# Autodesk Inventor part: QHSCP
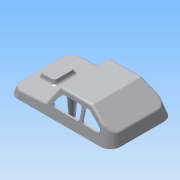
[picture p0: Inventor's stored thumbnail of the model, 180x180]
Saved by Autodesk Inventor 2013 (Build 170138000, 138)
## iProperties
Created: 2015-05
Part Number: QHSCP
Material: ABS 플라스틱
Document SubType Name: Modeling
Designer: WINDOWS7
Density: 1.06 g/cm^3
Mass: 32.8898 g
Surface Area: 297.469 cm^2
Volume: 31.0281 cm^3
Author: WINDOWS7
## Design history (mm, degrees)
sketch "스케치1"
  geometry: L1 (0, 0)-(122, 0); L2 (122, 0)-(122, 76); L3 (122, 76)-(0, 76); L4 (0, 76)-(0, 0)
  constraints: 8 end point, 2 parallel, 1 horizontal, 1 perpendicular
  dimensions: "d1" = 122 distance of L1.start L1.end; "d2" = 76 distance of L3.end L1.start
extrude "돌출1" new body sketch "스케치1" distance "d3" = 9; taper "d4" = 0 deg
sketch "스케치2"
  geometry: L1 (0, 0)-(122, 0) reference; L2 (0, 9)-(122, 9) reference; L3 (0, 0)-(0, 9) reference; L4 (0, 9)-(42, 11.201); L5 (42, 11.201)-(54.372, 31); L6 (122, 0)-(118.412, 13.392); L7 (54.372, 31)-(92, 31); L8 (92, 31)-(122, 11); L9 (122, 0)-(122, 9) reference; L10 (119.588, 9)-(122, 9); L11 (122, 9)-(122, 0); 1 further point
  constraints: 14 end point, 4 point on line, 2 perpendicular, 1 collinear, 1 vertical alignment
  dimensions: "d5" = 3 deg angle of L2 L4; "d7" = 42 horizontal distance of L2.start L4.end; "d8" = 125 deg angle of L5 L4; "d9" = 31 distance from line of L1 L5.end; "d10" = 105 deg angle of L1 L6; "d11" = 30 horizontal distance of L7.end L1.end; "d13" = 20 distance from line of L7 point (122, 11); "d16" = 123.69 deg angle of L8 L9
extrude "돌출2" join sketch "스케치2" stored distance "d14" = 8; taper "d15" = 0 deg
extrude "돌출3" cut sketch "스케치2" stored distance "d17" = 8; taper "d18" = 0 deg
sketch "스케치3"
  geometry: L1 (0, 0)-(-122, 0) reference; L2 (0, 76)-(0, 0) reference; L3 (-122, 76)-(0, 76) reference; L4 (-122, 0)-(-122, 76) reference; L5 (-62.899, 88.126)-(-62.899, -13.455); L6 (-92, 76)-(-54.372, 76) reference
  constraints: 2 end point, 1 perpendicular
  dimensions: "d19" = 62.8987 distance between parallel lines of L2 L5; "d20" = 88.12563 distance from line of L5.start L1; "d21" = 13.45472 distance from line of L5.end L1
node "작업 평면1"
sketch "스케치4"
  geometry: L1 (104.027, 0)-(-0.312, 0); L2 (-0.312, 0)-(-0.312, -61.792); L3 (-0.312, -61.792)-(104.027, -61.792); L4 (104.027, -61.792)-(104.027, 0); L5 (88.126, 0)-(72.7, -57.568); L6 (72.7, -57.568)-(27.551, -57.568); L7 (12.126, 0)-(88.126, 0) reference; L8 (27.551, -57.568)-(12.126, 0)
  constraints: 14 end point, 3 parallel, 1 horizontal, 1 perpendicular
  dimensions: "d23" = 105 deg angle of L5 L1; "d24" = 105 deg angle of L1 L8; "d25" = 0 distance between parallel lines of L1 L7; "d26" = 61.79173 distance between parallel lines of L3 L7; "d27" = 57.56843 distance between parallel lines of L6 L7; "d28" = 104.3385 distance between parallel lines of L2 L4; "d29" = 15.90095 distance from line of L5.start L4
extrude "돌출4" cut sketch "스케치4" stored distance "d30" = 8; taper "d31" = 0 deg
sketch "스케치5"
  geometry: L1 (0, 0)-(-122, 0) reference; L2 (0, 76)-(0, 0) reference; L3 (-122, 76)-(0, 76) reference; L4 (-122, 0)-(-122, 76) reference; L5 (-122, 38)-(0, 38)
  constraints: 2 end point, 2 midpoint
node "작업 평면2"
sketch "스케치7"
  geometry: L1 (122, 0)-(119.554, -9.128); L2 (122, 0)-(0, 0) reference; L3 (122, -9)-(80, -11.201) reference; L4 (122, 0)-(119.554, 0); L5 (119.554, 0)-(119.554, -9.128); L6 (119.554, -9.128)-(122, -9.128); L7 (122, -9.128)-(122, 0)
  constraints: 10 end point, 2 parallel, 1 horizontal, 1 perpendicular, 1 point on line
  dimensions: "d40" = 105 deg angle of L1 L2
extrude "돌출6" cut sketch "스케치7" stored distance "d41" = 26; taper "d42" = 0 deg
sketch "스케치8"
  geometry: L1 (76, 0)-(0, 0) reference; L2 (8.306, 31)-(67.694, 31) reference; L3 (8.306, 31)-(67.694, 31) reference; C1 r 4 at (59, 0); C2 r 4 at (48, 0); C3 r 4 at (28, 0); C4 r 4 at (17, 0); 1 further point
  constraints: 4 centre point, 4 point on line, 3 equal radius, 1 midpoint
  dimensions: "d43" = 8 diameter of C1; "d45" = 11 distance of C4.centre C3.centre; "d46" = 11 distance of C2.centre C1.centre; "d47" = 20 distance of C3.centre C2.centre; "d48" = 10 horizontal distance of C2.centre point (38, 31)
extrude "돌출7" join sketch "스케치8" stored distance "d49" = 4; taper "d50" = 0 deg
sketch "스케치9"
  geometry: L1 (122, 0)-(0, 0) reference; L2 (114.644, 0)-(130.381, 0); L3 (130.381, 0)-(130.381, 5.483); L4 (130.381, 5.483)-(114.644, 5.483); L5 (114.644, 5.483)-(114.644, 0)
  constraints: 8 end point, 2 parallel, 1 horizontal, 1 perpendicular, 1 point on line
  dimensions: "d51" = 5.48259 distance between parallel lines of L4 L1; "d52" = 15.73649 distance between parallel lines of L3 L5; "d53" = 8.38057 distance from line of L1.start L3
extrude "돌출8" cut sketch "스케치9" stored distance "d54" = 4; taper "d55" = 0 deg
sketch "스케치10"
  geometry: L1 (74.23, -11)-(40.23, -11); L2 (40.23, -11)-(40.23, -26); L3 (40.23, -26)-(64.857, -26); L4 (64.857, -26)-(74.23, -11); L5 (30, -31)-(67.628, -31) reference; L6 (67.628, -31)-(80, -11.201) reference; L7 (3.588, -13.392)-(30, -31) reference; L8 (37.014, -26)-(37.014, -11); L9 (37.014, -11)-(9.014, -11); L10 (31.514, -26)-(9.014, -11); L11 (37.014, -26)-(31.514, -26); 1 further point
  constraints: 16 end point, 4 parallel, 3 perpendicular, 1 horizontal, 1 horizontal alignment
  dimensions: "d56" = 34 distance of L1.start L1.end; "d58" = 15 distance between parallel lines of L1 L3; "d59" = 5 distance between parallel lines of L5 L3; "d60" = 5 distance between parallel lines of L6 L4; "d63" = 28 distance of L8.end L9.end; "d64" = 5 distance between parallel lines of L7 L10; "d65" = 15 distance between parallel lines of L9 L11
extrude "돌출9" cut sketch "스케치10" stored distance "d66" = 4; taper "d67" = 0 deg
fillet "모깎기1" dims "d68" = 3
sketch "스케치12"
  geometry: L1 (-31.529, 48.734)-(-11.529, 48.734); L2 (-11.529, 48.734)-(-11.529, 22.734); L3 (-11.529, 22.734)-(-31.529, 22.734); L4 (-31.529, 22.734)-(-31.529, 48.734); L5 (-42.529, 40.999)-(-42.529, 28.999) reference; 1 further point
  constraints: 8 end point, 2 parallel, 1 horizontal, 1 perpendicular
  dimensions: "d81" = 26 distance of L3.end L1.start; "d83" = 20 distance between parallel lines of L2 L4; "d84" = 11 distance between parallel lines of L5 L4
extrude "돌출10" join sketch "스케치12" distance "d85" = 5; taper "d86" = -15 deg
sketch "스케치13"
  geometry: L1 (-11.529, 48.734)-(-11.529, 22.734) reference; L2 (-11.529, 22.734)-(-31.529, 22.734) reference; L3 (-31.529, 22.734)-(-31.529, 48.734) reference; L4 (-31.529, 48.734)-(-11.529, 48.734) reference; L5 (-29.529, 24.734)-(-13.529, 24.734); L6 (-13.529, 24.734)-(-13.529, 46.734); L7 (-13.529, 46.734)-(-29.529, 46.734); L8 (-29.529, 46.734)-(-29.529, 24.734); 1 further point
  constraints: 8 end point, 2 parallel, 1 horizontal, 1 perpendicular
  dimensions: "d87" = 2 distance between parallel lines of L3 L8; "d88" = 2 distance between parallel lines of L2 L5; "d89" = 2 distance between parallel lines of L7 L4; "d90" = 2 distance between parallel lines of L1 L6
extrude "돌출11" cut sketch "스케치13" distance "d91" = 3; taper "d92" = -15 deg
sketch "스케치14"
  geometry: L1 (-122, 76)-(0, 76) reference; L2 (-122, 0)-(-122, 76) reference; L3 (0, 0)-(-122, 0) reference; L4 (0, 13)-(0, 0) reference; L5 (-120, 74)-(-2, 74); L6 (-2, 74)-(-2, 2); L7 (-2, 2)-(-120, 2); L8 (-120, 2)-(-120, 74)
  constraints: 8 end point, 2 parallel, 1 horizontal, 1 perpendicular
  dimensions: "d93" = 2 distance between parallel lines of L1 L5; "d94" = 2 distance between parallel lines of L2 L8; "d95" = 2 distance between parallel lines of L3 L7; "d96" = 2 distance between parallel lines of L4 L6
extrude "돌출12" cut sketch "스케치14" distance "d97" = 7; taper "d98" = -15 deg
sketch "스케치16"
  geometry: L1 (32.422, -26)-(34.014, -26) reference; L2 (37.014, -23)-(37.014, -14) reference; L3 (34.014, -11)-(18.922, -11) reference; L4 (17.258, -16.496)-(30.758, -25.496) reference; L5 (65.738, -24.59)-(71.362, -15.59) reference; L6 (68.818, -11)-(43.23, -11) reference; L7 (40.23, -14)-(40.23, -23) reference; L8 (43.23, -26)-(63.194, -26) reference; L9 (122, 0)-(119.554, -9.128) reference; L10 (80, -11.201)-(119.554, -9.128) reference; L11 (67.628, -31)-(80, -11.201) reference; L12 (30, -31)-(67.628, -31) reference; L13 (3.588, -13.392)-(30, -31) reference; L14 (0, 0)-(3.588, -13.392) reference; L15 (0, 0)-(122, 0) reference; L16 (120, 0)-(118.124, -7) reference; A1 r 3 centre (34.014, -23) between (34.014, -26) and (37.014, -23) reference; A2 r 3 centre (34.014, -14) between (37.014, -14) and (34.014, -11) reference; A3 r 3 centre (18.922, -14) between (18.922, -11) and (17.258, -16.496) reference; A4 r 3 centre (32.422, -23) between (30.758, -25.496) and (32.422, -26) reference; A5 r 3 centre (68.818, -14) between (71.362, -15.59) and (68.818, -11) reference; A6 r 3 centre (43.23, -14) between (43.23, -11) and (40.23, -14) reference; A7 r 3 centre (43.23, -23) between (40.23, -23) and (43.23, -26) reference; A8 r 3 centre (63.194, -23) between (63.194, -26) and (65.738, -24.59) reference; 1 further point
  node "투영된 루프1"
sketch "스케치17"
  geometry: L1 (118.124, -7)-(78.985, -9.051); L2 (80, -11.201)-(119.554, -9.128) reference; L3 (67.628, -31)-(80, -11.201) reference; L4 (66.52, -29)-(30.606, -29); L5 (43.23, -26)-(63.194, -26) reference; L6 (30, -31)-(67.628, -31) reference; L7 (3.588, -13.392)-(30, -31) reference; L8 (30.606, -29)-(5.239, -12.089); L9 (5.239, -12.089)-(2, 0); L10 (2, 0)-(3.876, -7) reference; L11 (0, 0)-(3.588, -13.392) reference; L12 (66.52, -29)-(78.985, -9.051); L13 (118.124, -7)-(120, 0); L14 (120, 0)-(118.124, -7) reference; L15 (120, 0)-(2, 0); L16 (2, 0)-(120, 0) reference; 1 further point
  constraints: 14 end point, 6 parallel, 3 collinear, 1 point on line
  dimensions: "d100" = 2 distance between parallel lines of L6 L4; "d101" = 2 distance between parallel lines of L8 L7; "d102" = 2 distance between parallel lines of L12 L3
extrude "돌출13" cut sketch "스케치17" stored distance "d103" = 70; taper "d104" = 0 deg
extrude "돌출14" cut sketch "스케치17" stored distance "d105" = 70; taper "d106" = 0 deg
sketch "스케치19"
  geometry: L1 (-11.529, 48.734)-(-11.529, 22.734) reference; L2 (-11.529, 22.734)-(-31.529, 22.734) reference; L3 (-31.529, 22.734)-(-31.529, 48.734) reference; L4 (-31.529, 48.734)-(-11.529, 48.734) reference; L5 (-13.529, 24.734)-(-29.529, 24.734); L6 (-29.529, 24.734)-(-29.529, 46.734); L7 (-29.529, 46.734)-(-13.529, 46.734); L8 (-13.529, 46.734)-(-13.529, 24.734); 1 further point
  constraints: 8 end point, 2 parallel, 1 horizontal, 1 perpendicular
  dimensions: "d115" = 2 distance between parallel lines of L4 L7; "d116" = 2 distance between parallel lines of L1 L8; "d117" = 2 distance between parallel lines of L2 L5; "d118" = 2 distance between parallel lines of L3 L6
extrude "돌출15" cut sketch "스케치19" distance "d119" = 70; taper "d120" = 15 deg
sketch "스케치20"
  geometry: L1 (-120, 2)-(-120, 74) reference; L2 (-120, 74)-(-2, 74) reference; L3 (-2, 74)-(-2, 2) reference; L4 (-2, 2)-(-120, 2) reference; L5 (-122, 76)-(-118.412, 72.412) reference; L6 (-2.446, 2.446)-(0, 0) reference; L7 (-121, 75)-(-1.223, 75); L8 (-1.223, 75)-(-1.223, 1.223); L9 (-1.223, 1.223)-(-121, 1.223); L10 (-121, 1.223)-(-121, 75); L11 (-123.776, 77.776)-(3.96, 77.776); L12 (3.96, 77.776)-(3.96, -3.96); L13 (3.96, -3.96)-(-123.776, -3.96); L14 (-123.776, -3.96)-(-123.776, 77.776)
  constraints: 16 end point, 4 parallel, 2 horizontal, 2 perpendicular, 1 midpoint, 1 point on line
  dimensions: "d121" = 1 distance between parallel lines of L2 L7
extrude "돌출16" cut sketch "스케치20" distance "d122" = 1; taper "d123" = 0 deg
fillet "모깎기2" dims "d124" = 12
fillet "모깎기13" dims "d138" = 12
fillet "모깎기3" dims "d125" = 12
fillet "모깎기4" dims "d126" = 3
fillet "모깎기5" dims "d127" = 3
fillet "모깎기6" dims "d128" = 3
fillet "모깎기7" dims "d129" = 3
fillet "모깎기8" dims "d130" = 3
fillet "모깎기9" dims "d131" = 3
fillet "모깎기10" dims "d132" = 3
fillet "모깎기11" dims "d133" = 3
fillet "모깎기12" dims "d134" = 3
sketch "스케치22"
  geometry: L1 (121.732, 11.859)-(121.732, 64.141) reference; C1 r 3 at (100.732, 38); 2 further points
  constraints: 1 centre point, 1 horizontal alignment, 1 midpoint
  dimensions: "d139" = 21 distance from line of L1 C1.centre; "d140" = 6 diameter of C1
extrude "돌출17" join sketch "스케치22" stored distance "d141" = 1; taper "d142" = 4 deg
sketch "스케치23"
  geometry: L1 (121.732, 11.859)-(121.732, 64.141) reference; C1 r 3 at (60.732, 16); C2 r 3 at (60.732, 60); C3 r 3 at (100.732, 38) reference; 1 further point
  constraints: 2 centre point, 1 equal radius, 1 vertical alignment
  dimensions: "d143" = 61 distance from line of L1 C1.centre; "d144" = 6 diameter of C1; "d145" = 22 vertical distance of C3.centre C2.centre; "d146" = 44 distance of C1.centre C2.centre
extrude "돌출18" join sketch "스케치23" stored distance "d147" = 1; taper "d148" = 4 deg
sketch "스케치24"
  geometry: C1 r 3 at (20.732, 38); C2 r 3 at (60.732, 16) reference; C3 r 3 at (100.732, 38) reference; 1 further point
  constraints: 1 centre point, 1 horizontal alignment
  dimensions: "d149" = 40 horizontal distance of C2.centre C1.centre; "d150" = 6 diameter of C1
extrude "돌출19" join sketch "스케치24" stored distance "d151" = 10; taper "d152" = 4 deg
sketch "스케치25"
  geometry: C1 r 3 at (0, 0) reference; C2 r 3 at (40, 22) reference; C3 r 3 at (80, 0) reference; C4 r 3 at (40, -22) reference; 1 further point
hole "구멍1" sketch "스케치25" at (80, 0), (40, 22), (0, 0), (40, -22) diameter "d153" = 3.242; stored, may be unused: countersink angle "d157" = 90 deg, drill point angle "d159" = 118 deg; dims "d154" = 9, "d155" = 4, "d156" = 2, "d158" = 11
node "솔리드1"
node "투영된 루프3"
node "투영된 루프4"
node "투영된 루프5"
other parameters: "d22" = 90 deg, "d32" = 90 deg
